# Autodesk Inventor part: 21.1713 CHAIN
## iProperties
Created: 2006-10
Document SubType Name: Modeling
Designer: Andy Moles
Part Number: 21.1713 CHAIN
Material: Steel
Mass: 1.54806 g
Surface Area: 5.08074 cm^2
Volume: 0.197205 cm^3
Density: 7.85 g/cm^3
Author: Andy Moles
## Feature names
1. Base1
2. Extrusion1
